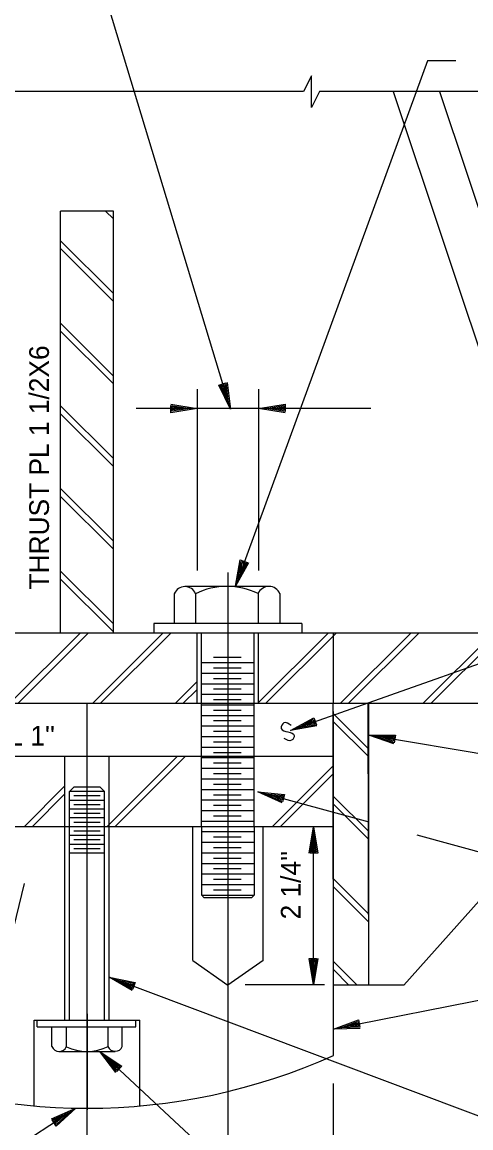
# Model space of a CAD drawing. Extents: x 0.04 to 6.71, y 0.04 to 4.71.
# Drawn here: x 3.679 to 4.21, y 0.973 to 2.283 of the extents above; entities that cross this region are included whole.
import ezdxf

# ---------------------------------------------------------------- set-up
doc = ezdxf.new("R2010")
doc.units = 0
for name, color, linetype in [('Level 13', 7, 'Continuous'), ('Level 25', 7, 'Continuous'), ('Level 3', 7, 'Continuous'), ('Level 50', 7, 'Continuous')]:
    doc.layers.add(name, color=color, linetype=linetype)

msp = doc.modelspace()

# ---------------------------------------------------------------- linework, layer by layer
at = {"layer": 'Level 13'}
for p, q in [((3.8856, 1.8252), (3.8135, 1.8252)), ((3.9585, 1.8252), (3.8856, 1.8252)), ((4.0911, 1.8252), (3.9585, 1.8252)), ((3.9709, 1.6142), (3.8711, 1.6142)), ((3.8586, 1.6058), (3.8586, 1.5705)), ((3.8839, 1.6059), (3.8839, 1.5705)), ((3.9578, 1.6061), (3.9578, 1.5705)), ((3.9836, 1.6058), (3.9836, 1.5705)), ((4.0096, 1.5705), (3.8346, 1.5705)), ((3.8346, 1.5705), (3.8346, 1.5589)), ((4.0096, 1.5589), (3.8346, 1.5589)), ((3.9836, 1.5705), (3.8586, 1.5705)), ((3.8908, 1.3297), (3.8908, 1.5589)), ((3.9533, 1.3297), (3.9533, 1.5589)), ((4.0096, 1.5705), (4.0096, 1.5589)), ((3.9533, 1.5238), (3.8908, 1.5238)), ((3.9376, 1.5301), (3.9049, 1.5301)), ((3.9533, 1.5113), (3.8908, 1.5113)), ((3.9376, 1.5175), (3.9049, 1.5175)), ((3.9533, 1.4987), (3.8908, 1.4987)), ((3.9376, 1.505), (3.9049, 1.505)), ((3.9533, 1.4863), (3.8908, 1.4863)), ((3.9376, 1.4925), (3.9049, 1.4925)), ((3.9376, 1.48), (3.9049, 1.48)), ((3.9533, 1.4737), (3.8908, 1.4737)), ((3.9376, 1.4675), (3.9049, 1.4675)), ((3.9533, 1.4612), (3.8908, 1.4612)), ((3.9376, 1.455), (3.9049, 1.455)), ((3.9533, 1.4488), (3.8908, 1.4488)), ((3.9376, 1.4425), (3.9049, 1.4425)), ((3.9376, 1.4425), (3.9049, 1.4425)), ((3.9376, 1.4425), (3.9049, 1.4425)), ((3.9376, 1.4425), (3.9049, 1.4425)), ((3.9533, 1.4362), (3.8908, 1.4362)), ((3.9376, 1.4299), (3.9049, 1.4299)), ((3.9533, 1.4237), (3.8908, 1.4237)), ((3.9376, 1.4174), (3.9049, 1.4174)), ((3.9533, 1.4112), (3.8908, 1.4112)), ((3.9376, 1.405), (3.9049, 1.405)), ((3.9533, 1.3987), (3.8908, 1.3987)), ((3.9376, 1.3924), (3.9049, 1.3924)), ((3.9533, 1.3862), (3.8908, 1.3862)), ((3.9376, 1.3799), (3.9049, 1.3799)), ((3.9376, 1.3799), (3.9049, 1.3799)), ((3.9376, 1.3799), (3.9049, 1.3799)), ((3.9533, 1.3736), (3.8908, 1.3736)), ((3.9376, 1.3673), (3.9049, 1.3673)), ((3.9533, 1.3612), (3.8908, 1.3612)), ((3.9376, 1.3548), (3.9049, 1.3548)), ((3.9533, 1.3486), (3.8908, 1.3486)), ((3.9533, 1.3361), (3.8908, 1.3361)), ((3.9376, 1.3424), (3.9049, 1.3424)), ((3.8908, 1.3297), (3.8908, 1.2489)), ((3.9533, 1.3237), (3.8908, 1.3237)), ((3.9376, 1.3298), (3.9049, 1.3298)), ((3.9533, 1.3297), (3.9533, 1.2487)), ((3.9533, 1.311), (3.8908, 1.311)), ((3.9376, 1.3173), (3.9049, 1.3173)), ((3.9376, 1.3173), (3.9049, 1.3173)), ((3.9533, 1.2986), (3.8908, 1.2986)), ((3.9376, 1.3048), (3.9049, 1.3048)), ((3.9533, 1.286), (3.8908, 1.286)), ((3.9376, 1.2923), (3.9049, 1.2923)), ((3.9533, 1.2735), (3.8908, 1.2735)), ((3.9376, 1.2798), (3.9049, 1.2798)), ((3.9533, 1.2611), (3.8908, 1.2611)), ((3.9376, 1.2673), (3.9049, 1.2673)), ((3.8908, 1.2489), (3.894, 1.2455)), ((3.9533, 1.2485), (3.8908, 1.2485)), ((3.95, 1.2455), (3.894, 1.2455)), ((3.9376, 1.2548), (3.9049, 1.2548)), ((3.9533, 1.2487), (3.95, 1.2455)), ((3.6964, 1.0928), (3.6964, 1.1006)), ((3.8131, 1.0928), (3.8131, 1.1006)), ((3.6964, 1.0928), (3.8131, 1.0928)), ((3.7137, 1.0693), (3.7137, 1.0928)), ((3.7309, 1.0691), (3.7309, 1.0928)), ((3.7802, 1.0692), (3.7802, 1.0928)), ((3.7971, 1.0693), (3.7971, 1.0928)), ((3.7222, 1.0637), (3.7887, 1.0637))]:
    msp.add_line(p, q, dxfattribs=at)
msp.add_lwpolyline([(4.0303, 2.2004), (4.021, 2.1817), (4.021, 2.2191), (4.0117, 2.2004)], dxfattribs=at)
for centre, radius, start, end in [((3.8712, 1.6004), 0.0137, 22.375, 157.1995), ((3.9211, 1.5289), 0.0854, 64.5519, 115.884), ((3.9707, 1.6002), 0.0141, 23.1675, 155.9991), ((3.7223, 1.073), 0.00938, 203.1675, 335.9991), ((3.7554, 1.1206), 0.0569, 244.5519, 295.884), ((3.7886, 1.0729), 0.00912, 202.375, 337.1995)]:
    msp.add_arc(centre, radius, start, end, dxfattribs=at)
at = {"layer": 'Level 25'}
for p, q in [((3.9252, 1.8244), (3.7649, 2.3543)), ((4.0117, 2.2004), (3.3459, 2.2004)), ((4.5103, 2.2004), (4.0303, 2.2004)), ((4.1177, 2.2004), (4.3315, 1.5589)), ((4.1726, 2.2004), (4.3864, 1.5589)), ((3.7241, 1.5589), (3.7241, 2.0589)), ((3.7866, 2.0589), (3.7241, 2.0589)), ((3.7866, 2.0497), (3.7774, 2.0589)), ((3.7866, 1.5589), (3.7866, 2.0589)), ((3.7866, 1.9613), (3.7241, 2.0238)), ((3.7866, 1.9519), (3.7241, 2.0144)), ((3.7866, 1.8635), (3.7241, 1.926)), ((3.7866, 1.8541), (3.7241, 1.9166)), ((3.8856, 1.8481), (3.8856, 1.6331)), ((3.9585, 1.8481), (3.9585, 1.6331)), ((3.7866, 1.7657), (3.7241, 1.8282)), ((3.8856, 1.8252), (3.8856, 1.8252)), ((3.9585, 1.8252), (3.9585, 1.8252)), ((3.7866, 1.7562), (3.7241, 1.8187)), ((3.7866, 1.6679), (3.7241, 1.7304)), ((3.7866, 1.6584), (3.7241, 1.7209)), ((3.7866, 1.57), (3.7241, 1.6325)), ((3.9221, 1.6307), (3.9221, 0.5778)), ((3.7866, 1.5606), (3.7241, 1.6231)), ((4.3864, 1.5589), (3.0688, 1.5589)), ((3.6638, 1.4756), (3.7472, 1.5589)), ((3.6733, 1.4756), (3.7566, 1.5589)), ((3.7617, 1.4756), (3.845, 1.5589)), ((3.7711, 1.4756), (3.8544, 1.5589)), ((3.8856, 1.4756), (3.8856, 1.5589)), ((3.9573, 1.4756), (4.0406, 1.5589)), ((3.9585, 1.4756), (3.9585, 1.5589)), ((3.9667, 1.4756), (4.0501, 1.5589)), ((4.0471, 1.4756), (4.0471, 1.5589)), ((4.0551, 1.4756), (4.1384, 1.5589)), ((4.0645, 1.4756), (4.1479, 1.5589)), ((4.1529, 1.4756), (4.2363, 1.5589)), ((4.1624, 1.4756), (4.2457, 1.5589)), ((3.8595, 1.4756), (3.8856, 1.5017)), ((3.8689, 1.4756), (3.8856, 1.4923)), ((4.3865, 1.4756), (3.0471, 1.4756)), ((3.7554, 0.5677), (3.7554, 1.4756)), ((4.0472, 1.0588), (4.0465, 1.4756)), ((4.0887, 1.1422), (4.0881, 1.4755)), ((4.0887, 1.1422), (4.0887, 1.4756)), ((4.0471, 1.0589), (4.0471, 1.4663)), ((4.0887, 1.4218), (4.0471, 1.4635)), ((4.0887, 1.4124), (4.0471, 1.4541)), ((4.4143, 1.3835), (4.0887, 1.4381)), ((4.3866, 1.43), (4.1304, 1.1422)), ((4.0471, 1.4131), (3.4637, 1.4131)), ((3.7293, 1.1006), (3.7293, 1.4131)), ((3.7789, 1.3297), (3.8622, 1.4131)), ((3.7814, 1.1006), (3.7814, 1.4131)), ((3.7883, 1.3297), (3.8717, 1.4131)), ((3.9745, 1.3297), (4.0471, 1.4023)), ((3.984, 1.3297), (4.0471, 1.3928)), ((3.6811, 1.3297), (3.7293, 1.378)), ((3.7346, 1.3714), (3.7398, 1.3766)), ((3.771, 1.3766), (3.7398, 1.3766)), ((3.7762, 1.3714), (3.771, 1.3766)), ((3.6905, 1.3297), (3.7293, 1.3686)), ((3.7346, 1.1006), (3.7346, 1.3714)), ((3.7762, 1.3714), (3.7346, 1.3714)), ((3.771, 1.3662), (3.7398, 1.3662)), ((3.7762, 1.1006), (3.7762, 1.3714)), ((4.0887, 1.324), (4.0471, 1.3657)), ((3.7762, 1.361), (3.7346, 1.361)), ((3.7762, 1.3506), (3.7346, 1.3506)), ((3.771, 1.3558), (3.7398, 1.3558)), ((4.0887, 1.3146), (4.0471, 1.3563)), ((3.7762, 1.3402), (3.7346, 1.3402)), ((3.771, 1.3454), (3.7398, 1.3454)), ((4.0471, 1.3297), (3.4637, 1.3297)), ((3.7762, 1.3297), (3.7346, 1.3297)), ((3.771, 1.3349), (3.7398, 1.3349)), ((3.771, 1.3245), (3.7398, 1.3245)), ((3.8804, 1.1714), (3.8804, 1.3297)), ((3.9637, 1.1714), (3.9637, 1.3297)), ((4.0235, 1.1424), (4.0232, 1.3297)), ((3.7762, 1.3193), (3.7346, 1.3193)), ((3.771, 1.3141), (3.7398, 1.3141)), ((3.7762, 1.3089), (3.7346, 1.3089)), ((3.7762, 1.2985), (3.7346, 1.2985)), ((3.771, 1.3037), (3.7398, 1.3037)), ((3.6208, 1.014), (3.6813, 1.2626)), ((4.0887, 1.2262), (4.0471, 1.2679)), ((4.0887, 1.2168), (4.0471, 1.2585)), ((3.8804, 1.1714), (3.9221, 1.1422)), ((3.9637, 1.1714), (3.9221, 1.1422)), ((4.0749, 1.1422), (4.0471, 1.1701)), ((4.0654, 1.1422), (4.0471, 1.1606)), ((4.0363, 1.1424), (3.9425, 1.1424)), ((4.1304, 1.1422), (4.047, 1.1421)), ((4.1304, 1.1422), (4.0471, 1.1422)), ((4.3068, 1.1413), (4.0471, 1.0899)), ((3.6929, 0.9992), (3.6929, 1.1006)), ((3.6929, 1.1006), (3.8179, 1.1006)), ((3.7554, 1.1083), (3.7554, 0.9946)), ((3.8179, 0.9992), (3.8179, 1.1006)), ((4.048, 0.4891), (4.0471, 1.0258)), ((3.4066, 0.7775), (3.7422, 0.9965))]:
    msp.add_line(p, q, dxfattribs=at)
msp.add_arc((3.7554, 1.7082), 0.7118, 245.8105, 294.1895, dxfattribs=at)
msp.add_spline([(3.9971, 1.4497), (3.9884, 1.4527), (3.9853, 1.4462), (4.0007, 1.4379), (3.9974, 1.4321), (3.9888, 1.4344)], degree=3, dxfattribs=at)
at = {"layer": 'Level 3'}
for p, q in [((3.9226, 1.8327), (3.9226, 1.8327)), ((3.9252, 1.8244), (3.9252, 1.8244)), ((3.9309, 1.6148), (3.9309, 1.6148)), ((3.9339, 1.6229), (3.9339, 1.6229)), ((3.9961, 1.4436), (3.9961, 1.4436)), ((4.0043, 1.4465), (4.0043, 1.4465)), ((3.9576, 1.3712), (3.9576, 1.3712)), ((3.9659, 1.3689), (3.9659, 1.3689))]:
    msp.add_line(p, q, dxfattribs=at)
for points in [[(4.1918, 2.2369), (4.1584, 2.2369), (3.9309, 1.6148)], [(3.9211, 1.8558), (3.9252, 1.8244), (3.9112, 1.8528), (3.9196, 1.8553), (3.9226, 1.8327), (3.9132, 1.852), (3.9186, 1.8536), (3.9202, 1.8407), (3.9151, 1.8512), (3.9174, 1.8519), (3.9177, 1.849)], [(3.9465, 1.6423), (3.9309, 1.6148), (3.9368, 1.6458), (3.9451, 1.6428), (3.9339, 1.6229), (3.9379, 1.644), (3.9432, 1.642), (3.9368, 1.6307), (3.939, 1.6422), (3.9412, 1.6414), (3.9398, 1.6389)], [(4.4472, 1.5716), (4.358, 1.5716), (3.9961, 1.4436)], [(4.0273, 1.4491), (3.9961, 1.4436), (4.0238, 1.4589), (4.0268, 1.4506), (4.0043, 1.4465), (4.0231, 1.4569), (4.025, 1.4515), (4.0122, 1.4493), (4.0224, 1.4548), (4.0232, 1.4526), (4.0203, 1.4522)], [(3.9863, 1.358), (3.9576, 1.3712), (3.989, 1.3679), (3.9866, 1.3594), (3.9659, 1.3689), (3.9873, 1.3667), (3.9858, 1.3612), (3.9739, 1.3667), (3.9855, 1.3654), (3.9849, 1.3632), (3.9823, 1.3644)], [(4.0894, 1.3351), (3.9576, 1.3712)], [(4.4569, 1.2577), (4.3725, 1.2577), (4.1461, 1.3196)], [(4.4569, 0.942), (4.3387, 0.942), (3.7814, 1.1515)], [(4.1997, 0.8444), (4.0051, 0.8444), (3.7704, 1.0637)]]:
    msp.add_lwpolyline(points, dxfattribs=at)
at = {"layer": 'Level 50'}
for p, q in [((3.8769, 1.8252), (3.8769, 1.8252)), ((3.8856, 1.8252), (3.8856, 1.8252)), ((3.9585, 1.8252), (3.9585, 1.8252)), ((3.9672, 1.8252), (3.9672, 1.8252)), ((4.0887, 1.4381), (4.0887, 1.4381)), ((4.0973, 1.4366), (4.0973, 1.4366)), ((4.0232, 1.3297), (4.0232, 1.3297)), ((4.0232, 1.3211), (4.0232, 1.3211)), ((3.7814, 1.1515), (3.7814, 1.1515)), ((3.7895, 1.1484), (3.7895, 1.1484)), ((4.0235, 1.1511), (4.0235, 1.1511)), ((4.0235, 1.1424), (4.0235, 1.1424)), ((4.0471, 1.0899), (4.0471, 1.0899)), ((4.0556, 1.0916), (4.0556, 1.0916)), ((3.7704, 1.0637), (3.7704, 1.0637)), ((3.7767, 1.0578), (3.7767, 1.0578)), ((3.7422, 0.9965), (3.7422, 0.9965)), ((3.7349, 0.9918), (3.7349, 0.9918))]:
    msp.add_line(p, q, dxfattribs=at)
for points in [[(3.8544, 1.8303), (3.8856, 1.8252), (3.8544, 1.82), (3.8544, 1.8288), (3.8769, 1.8252), (3.8558, 1.8217), (3.8558, 1.8273), (3.8686, 1.8252), (3.8571, 1.8233), (3.8571, 1.8257), (3.8599, 1.8252)], [(3.9897, 1.82), (3.9585, 1.8252), (3.9897, 1.8303), (3.9897, 1.8215), (3.9672, 1.8252), (3.9883, 1.8287), (3.9883, 1.823), (3.9755, 1.8252), (3.987, 1.827), (3.987, 1.8247), (3.9842, 1.8252)], [(4.1186, 1.4278), (4.0887, 1.4381), (4.1203, 1.438), (4.1189, 1.4293), (4.0973, 1.4366), (4.1187, 1.4366), (4.1178, 1.431), (4.1055, 1.4353), (4.1171, 1.4352), (4.1167, 1.4329), (4.114, 1.4338)], [(4.0181, 1.2986), (4.0232, 1.3297), (4.0284, 1.2986), (4.0196, 1.2986), (4.0232, 1.3211), (4.0267, 1.2999), (4.0211, 1.2999), (4.0232, 1.3127), (4.0251, 1.3012), (4.0227, 1.3012), (4.0232, 1.3041)], [(4.0286, 1.1736), (4.0235, 1.1424), (4.0183, 1.1736), (4.0271, 1.1736), (4.0235, 1.1511), (4.0199, 1.1722), (4.0256, 1.1723), (4.0235, 1.1594), (4.0216, 1.1709), (4.0239, 1.1709), (4.0235, 1.1681)], [(3.8088, 1.1357), (3.7814, 1.1515), (3.8124, 1.1454), (3.8093, 1.1371), (3.7895, 1.1484), (3.8106, 1.1443), (3.8086, 1.139), (3.7973, 1.1455), (3.8088, 1.1432), (3.8079, 1.141), (3.8054, 1.1425)], [(4.0787, 1.0909), (4.0471, 1.0899), (4.0767, 1.101), (4.0784, 1.0924), (4.0556, 1.0916), (4.0757, 1.0991), (4.0768, 1.0936), (4.0638, 1.0932), (4.0747, 1.0972), (4.0752, 1.0949), (4.0723, 1.0949)], [(3.7896, 1.0386), (3.7704, 1.0637), (3.7967, 1.0462), (3.7906, 1.0397), (3.7767, 1.0578), (3.7945, 1.0459), (3.7907, 1.0418), (3.7828, 1.0521), (3.7924, 1.0456), (3.7908, 1.0439), (3.7891, 1.0462)], [(3.7133, 0.9838), (3.7422, 0.9965), (3.7189, 0.9752), (3.7141, 0.9826), (3.7349, 0.9918), (3.7191, 0.9773), (3.716, 0.982), (3.7279, 0.9872), (3.7193, 0.9794), (3.718, 0.9814), (3.7207, 0.9825)]]:
    msp.add_lwpolyline(points, dxfattribs=at)

# ---------------------------------------------------------------- texts
at = {"layer": 'Level 25'}
for s, height, p in [('THRUST PL 1 1/2X6', 0.023292, (3.7103, 1.6107)), ("2 1/4''", 0.02329, (4.0081, 1.22))]:
    msp.add_text(s, height=height, rotation=90, dxfattribs=at).set_placement(p)
msp.add_text("PL 1''", height=0.02329, dxfattribs=at).set_placement((3.6415, 1.4259))

doc.saveas('drawing.dxf')
